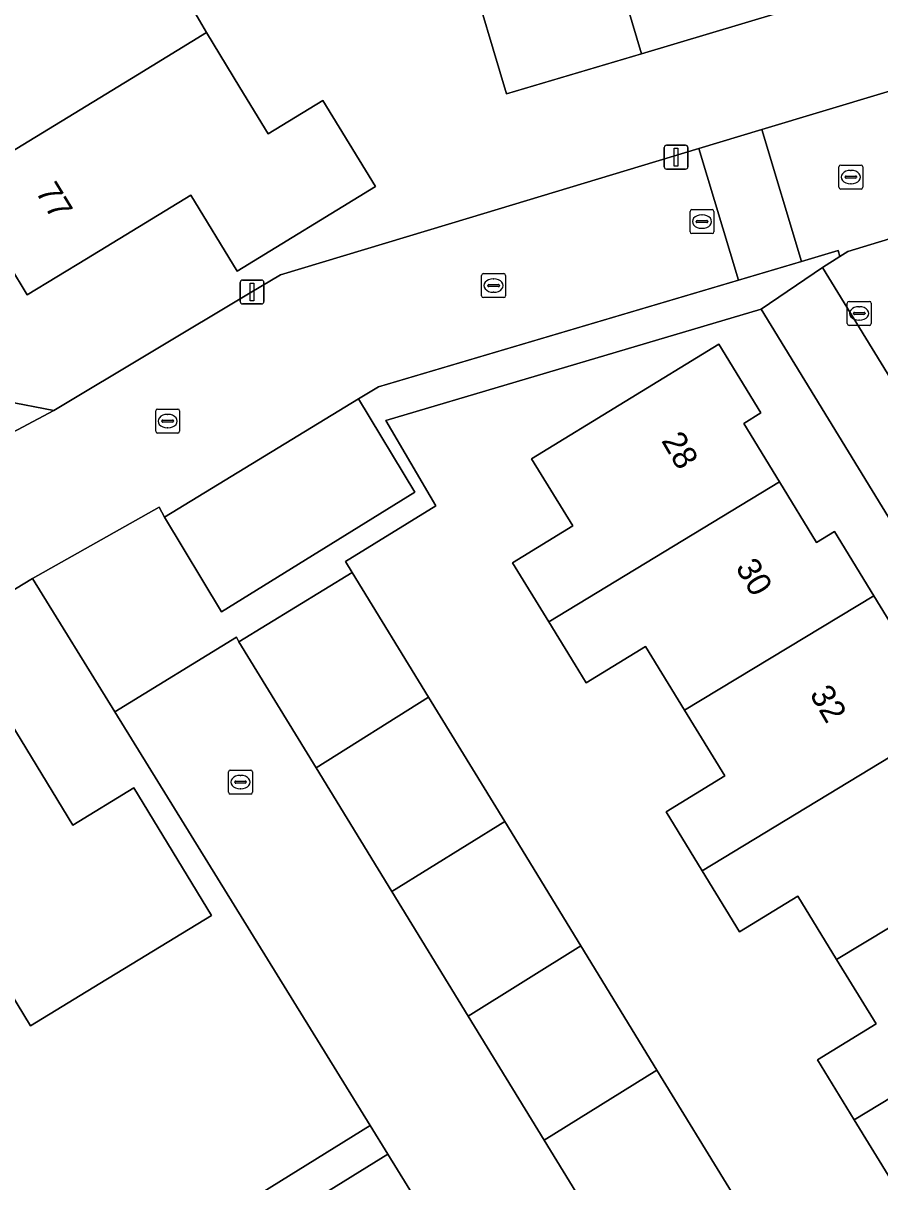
# Model space of a CAD drawing. Extents: x 157767 to 159172, y 387839 to 389425.
# Drawn here: x 158329.78 to 158365.56, y 388439.77 to 388488.15 of the extents above; entities that cross this region are included whole.
import ezdxf

# ---------------------------------------------------------------- set-up
doc = ezdxf.new("R2010")
doc.units = 0
for name, color, linetype in [('IMGEO_Erf', 7, 'Continuous'), ('IMGEO_Groenvoorziening', 7, 'Continuous'), ('IMGEO_Kolk', 7, 'Continuous'), ('IMGEO_Lichtmast', 7, 'Continuous'), ('IMGEO_Muur', 7, 'Continuous'), ('IMGEO_Pand', 7, 'Continuous'), ('IMGEO_Pand_nummerreeks', 7, 'Continuous'), ('IMGEO_Parkeervlak_open', 7, 'Continuous'), ('IMGEO_Rijbaan_lokaal_open', 7, 'Continuous'), ('IMGEO_Rioolput', 7, 'Continuous'), ('IMGEO_Voetpad_open', 7, 'Continuous')]:
    doc.layers.add(name, color=color, linetype=linetype)

msp = doc.modelspace()

# ---------------------------------------------------------------- linework, layer by layer
at = {"layer": 'IMGEO_Erf'}
for points in [[(158366.103, 388530.873), (158360.131, 388540.602), (158358.142, 388543.842), (158322.626, 388522.238), (158314.356, 388517.207), (158305.25, 388511.668), (158312.315, 388500), (158328.006, 388474.085), (158329.045, 388472.369), (158331.064, 388471.977), (158339.268, 388476.896), (158340.523, 388477.649), (158348.428, 388480.03), (158358.003, 388482.915), (158360.636, 388483.708), (158378.748, 388489.164), (158379.851, 388490.943), (158379.808, 388491.087), (158377.122, 388500)], [(158361.287, 388488.568), (158355.6, 388486.877), (158349.963, 388485.2), (158348.337, 388490.669)], [(158336.175, 388489.943), (158337.431, 388487.759), (158338.833, 388485.461), (158340.011, 388483.53), (158342.296, 388484.924), (158344.491, 388481.327), (158338.715, 388477.802), (158336.782, 388480.97), (158332.421, 388478.309), (158329.954, 388476.803), (158329.204, 388478.033), (158328.914, 388477.856), (158328.289, 388478.881), (158328.58, 388479.059), (158327.113, 388481.461), (158324.343, 388485.996), (158331.209, 388490.187)], [(158387.122, 388432.9), (158360.606, 388476.208), (158355.812, 388474.787), (158344.923, 388471.558), (158347.021, 388467.993), (158343.245, 388465.675), (158343.518, 388465.214), (158346.711, 388460.003), (158349.892, 388454.812), (158353.074, 388449.619), (158356.25, 388444.435), (158359.407, 388439.283), (158362.687, 388433.93), (158357.959, 388431.033), (158358.692, 388429.898), (158361.544, 388425.275), (158364.397, 388420.65), (158359.169, 388417.424), (158356.304, 388422.069), (158353.464, 388426.673), (158353.717, 388426.829), (158345.01, 388440.931), (158327.37, 388430.016)], [(158366.012, 388439.874), (158364.49, 388442.359), (158362.954, 388444.865), (158365.4, 388446.364), (158363.749, 388449.058), (158362.131, 388451.699), (158359.7, 388450.209), (158358.134, 388452.764), (158356.631, 388455.218), (158359.087, 388456.723), (158357.404, 388459.47), (158355.775, 388462.128), (158353.297, 388460.609), (158352.836, 388461.362), (158351.739, 388463.153), (158350.224, 388465.625), (158352.735, 388467.164), (158351.017, 388469.967), (158358.834, 388474.756), (158360.595, 388471.88), (158359.874, 388471.438), (158361.367, 388469.002), (158362.915, 388466.474), (158363.659, 388466.93), (158365.308, 388464.239), (158367.006, 388461.467)], [(158328.833, 388459.635), (158331.861, 388454.669), (158334.402, 388456.218), (158337.647, 388450.897), (158333.378, 388448.295), (158333.235, 388448.207), (158330.088, 388446.289), (158328.645, 388448.655)]]:
    msp.add_lwpolyline(points, dxfattribs=at)
msp.add_lwpolyline([(158334.852, 388436.275), (158344.271, 388442.128), (158333.608, 388459.397), (158330.168, 388464.968), (158255.92, 388419.848), (158255.073, 388417.271), (158254.463, 388415.416), (158258.254, 388409.185), (158259.825, 388406.604), (158265.321, 388397.571), (158266.938, 388394.918), (158298.48, 388413.756), (158296.533, 388416.95), (158304.157, 388421.599), (158306.105, 388418.404)], close=True, dxfattribs=at)
at = {"layer": 'IMGEO_Groenvoorziening'}
msp.add_lwpolyline([(158374.394, 388481.687), (158366.919, 388479.436), (158364.221, 388478.624), (158363.886, 388478.411), (158363.169, 388477.953), (158368.328, 388469.526)], dxfattribs=at)
at = {"layer": 'IMGEO_Kolk'}
for p, q in [((158363.849, 388481.3), (158363.849, 388482.152)), ((158363.924, 388482.226), (158364.776, 388482.226)), ((158364.85, 388482.152), (158364.85, 388481.3)), ((158364.108, 388481.72), (158364.108, 388481.732)), ((158364.546, 388481.683), (158364.148, 388481.683)), ((158364.151, 388481.769), (158364.549, 388481.769)), ((158364.337, 388482.006), (158364.362, 388482.006)), ((158364.592, 388481.732), (158364.592, 388481.72)), ((158364.776, 388481.226), (158363.924, 388481.226)), ((158364.36, 388481.446), (158364.335, 388481.446)), ((158348.927, 388476.77), (158348.927, 388477.622)), ((158349.002, 388477.696), (158349.854, 388477.696)), ((158349.229, 388477.239), (158349.627, 388477.239)), ((158349.415, 388477.476), (158349.44, 388477.476)), ((158349.928, 388477.622), (158349.928, 388476.77)), ((158349.186, 388477.19), (158349.186, 388477.202)), ((158349.624, 388477.153), (158349.226, 388477.153)), ((158349.438, 388476.916), (158349.413, 388476.916)), ((158349.67, 388477.202), (158349.67, 388477.19)), ((158349.854, 388476.696), (158349.002, 388476.696)), ((158335.315, 388471.111), (158335.315, 388471.963)), ((158335.39, 388472.037), (158336.242, 388472.037)), ((158336.316, 388471.963), (158336.316, 388471.111)), ((158335.574, 388471.531), (158335.574, 388471.543)), ((158336.012, 388471.494), (158335.614, 388471.494)), ((158335.617, 388471.58), (158336.015, 388471.58)), ((158335.803, 388471.817), (158335.828, 388471.817)), ((158336.058, 388471.543), (158336.058, 388471.531)), ((158336.242, 388471.037), (158335.39, 388471.037)), ((158335.826, 388471.257), (158335.801, 388471.257)), ((158338.432, 388456.963), (158339.284, 388456.963)), ((158338.357, 388456.037), (158338.357, 388456.889)), ((158338.616, 388456.457), (158338.616, 388456.469)), ((158339.054, 388456.42), (158338.656, 388456.42)), ((158338.659, 388456.506), (158339.057, 388456.506)), ((158338.845, 388456.743), (158338.87, 388456.743)), ((158339.1, 388456.469), (158339.1, 388456.457)), ((158339.358, 388456.889), (158339.358, 388456.037)), ((158339.284, 388455.963), (158338.432, 388455.963)), ((158338.868, 388456.183), (158338.843, 388456.183))]:
    msp.add_line(p, q, dxfattribs=at)
for points in [[(158363.849, 388481.3), (158363.849, 388482.152)], [(158363.924, 388482.226), (158364.776, 388482.226)], [(158364.85, 388482.152), (158364.85, 388481.3)], [(158364.776, 388481.226), (158363.924, 388481.226)], [(158348.927, 388476.77), (158348.927, 388477.622)], [(158349.002, 388477.696), (158349.854, 388477.696)], [(158349.928, 388477.622), (158349.928, 388476.77)], [(158349.854, 388476.696), (158349.002, 388476.696)], [(158335.315, 388471.111), (158335.315, 388471.963)], [(158335.39, 388472.037), (158336.242, 388472.037)], [(158336.316, 388471.963), (158336.316, 388471.111)], [(158336.242, 388471.037), (158335.39, 388471.037)], [(158338.432, 388456.963), (158339.284, 388456.963)], [(158338.357, 388456.037), (158338.357, 388456.889)], [(158339.358, 388456.889), (158339.358, 388456.037)], [(158339.284, 388455.963), (158338.432, 388455.963)]]:
    msp.add_lwpolyline(points, dxfattribs=at)
for centre, radius, start, end in [((158363.926, 388482.15), 0.0765, 91.552, 178.448), ((158363.926, 388482.15), 0.0765, 91.552, 178.448), ((158364.774, 388482.15), 0.0765, 1.552, 88.448), ((158364.774, 388482.15), 0.0765, 1.552, 88.448), ((158364.148, 388481.729), 0.0403, 85.8775, 175.7526), ((158364.145, 388481.719), 0.0366, 178.938, 274.7102), ((158364.549, 388481.726), 0.043, 264.8664, 352.4533), ((158364.553, 388481.731), 0.0386, 1.7309, 96.639), ((158363.926, 388481.302), 0.0765, 181.552, 268.448), ((158363.926, 388481.302), 0.0765, 181.552, 268.448), ((158364.774, 388481.302), 0.0765, 271.552, 358.448), ((158364.774, 388481.302), 0.0765, 271.552, 358.448), ((158349.004, 388477.62), 0.0765, 91.552, 178.448), ((158349.004, 388477.62), 0.0765, 91.552, 178.448), ((158349.226, 388477.199), 0.0403, 85.8775, 175.7526), ((158349.631, 388477.201), 0.0386, 1.7309, 96.639), ((158349.852, 388477.62), 0.0765, 1.552, 88.448), ((158349.852, 388477.62), 0.0765, 1.552, 88.448), ((158349.004, 388476.772), 0.0765, 181.552, 268.448), ((158349.004, 388476.772), 0.0765, 181.552, 268.448), ((158349.223, 388477.189), 0.0366, 178.938, 274.7102), ((158349.627, 388477.196), 0.043, 264.8664, 352.4533), ((158349.852, 388476.772), 0.0765, 271.552, 358.448), ((158349.852, 388476.772), 0.0765, 271.552, 358.448), ((158335.392, 388471.961), 0.0765, 91.552, 178.448), ((158335.392, 388471.961), 0.0765, 91.552, 178.448), ((158336.24, 388471.961), 0.0765, 1.552, 88.448), ((158336.24, 388471.961), 0.0765, 1.552, 88.448), ((158335.614, 388471.54), 0.0403, 85.8775, 175.7526), ((158335.611, 388471.53), 0.0366, 178.938, 274.7102), ((158336.015, 388471.537), 0.043, 264.8664, 352.4533), ((158336.019, 388471.542), 0.0386, 1.7309, 96.639), ((158335.392, 388471.113), 0.0765, 181.552, 268.448), ((158335.392, 388471.113), 0.0765, 181.552, 268.448), ((158336.24, 388471.113), 0.0765, 271.552, 358.448), ((158336.24, 388471.113), 0.0765, 271.552, 358.448), ((158338.434, 388456.887), 0.0765, 91.552, 178.448), ((158338.434, 388456.887), 0.0765, 91.552, 178.448), ((158339.282, 388456.887), 0.0765, 1.552, 88.448), ((158339.282, 388456.887), 0.0765, 1.552, 88.448), ((158338.656, 388456.466), 0.0403, 85.8775, 175.7526), ((158338.653, 388456.456), 0.0366, 178.938, 274.7102), ((158339.057, 388456.463), 0.043, 264.8664, 352.4533), ((158339.061, 388456.468), 0.0386, 1.7309, 96.639), ((158338.434, 388456.039), 0.0765, 181.552, 268.448), ((158338.434, 388456.039), 0.0765, 181.552, 268.448), ((158339.282, 388456.039), 0.0765, 271.552, 358.448), ((158339.282, 388456.039), 0.0765, 271.552, 358.448)]:
    msp.add_arc(centre, radius, start, end, dxfattribs=at)
for centre, major_axis, ratio, start_param, end_param in [((158364.336, 388481.726), (-0.387, 0.002), 0.722429, 4.712389, 7.853982), ((158364.361, 388481.726), (-0.39, 0.002), 0.717154, 1.570796, 4.712389), ((158349.414, 388477.196), (-0.387, 0.002), 0.722429, 4.712389, 7.853982), ((158349.439, 388477.196), (-0.39, 0.002), 0.717154, 1.570796, 4.712389), ((158335.802, 388471.537), (-0.387, 0.002), 0.722429, 4.712389, 7.853982), ((158335.827, 388471.537), (-0.39, 0.002), 0.717154, 1.570796, 4.712389), ((158338.844, 388456.463), (-0.387, 0.002), 0.722429, 4.712389, 7.853982), ((158338.869, 388456.463), (-0.39, 0.002), 0.717154, 1.570796, 4.712389)]:
    msp.add_ellipse(centre, major_axis=major_axis, ratio=ratio, start_param=start_param, end_param=end_param, dxfattribs=at)
at = {"layer": 'IMGEO_Lichtmast'}
for p, q in [((158356.652, 388483.057), (158357.442, 388483.057)), ((158357.442, 388483.057), (158356.652, 388483.057)), ((158356.552, 388482.157), (158356.552, 388482.957)), ((158356.552, 388482.957), (158356.552, 388482.157)), ((158357.542, 388482.957), (158357.542, 388482.157)), ((158357.542, 388482.157), (158357.542, 388482.957)), ((158357.442, 388482.057), (158356.652, 388482.057)), ((158356.652, 388482.057), (158357.442, 388482.057)), ((158338.847, 388476.528), (158338.847, 388477.328)), ((158338.847, 388477.328), (158338.847, 388476.528)), ((158338.947, 388477.428), (158339.737, 388477.428)), ((158339.737, 388477.428), (158338.947, 388477.428)), ((158339.837, 388477.328), (158339.837, 388476.528)), ((158339.837, 388476.528), (158339.837, 388477.328)), ((158339.737, 388476.428), (158338.947, 388476.428)), ((158338.947, 388476.428), (158339.737, 388476.428))]:
    msp.add_line(p, q, dxfattribs=at)
for points in [[(158356.972, 388482.932), (158357.122, 388482.932), (158357.122, 388482.182), (158356.972, 388482.182), (158356.972, 388482.932)], [(158339.267, 388477.303), (158339.417, 388477.303), (158339.417, 388476.553), (158339.267, 388476.553), (158339.267, 388477.303)]]:
    msp.add_lwpolyline(points, dxfattribs=at)
for centre, start, end in [((158356.652, 388482.957), 90, 180), ((158356.652, 388482.957), 90, 180), ((158357.442, 388482.957), 0, 90), ((158357.442, 388482.957), 360, 90), ((158356.652, 388482.157), 180, 270), ((158356.652, 388482.157), 180, 270), ((158357.442, 388482.157), 270, 0), ((158357.442, 388482.157), 270, 0), ((158338.947, 388477.328), 90, 180), ((158338.947, 388477.328), 90, 180), ((158339.737, 388477.328), 0, 90), ((158339.737, 388477.328), 360, 90), ((158338.947, 388476.528), 180, 270), ((158338.947, 388476.528), 180, 270), ((158339.737, 388476.528), 270, 0), ((158339.737, 388476.528), 270, 0)]:
    msp.add_arc(centre, 0.1, start, end, dxfattribs=at)
at = {"layer": 'IMGEO_Muur'}
for points in [[(158339.268, 388476.896), (158340.523, 388477.649), (158348.428, 388480.03)], [(158355.812, 388474.787), (158344.923, 388471.558), (158347.021, 388467.993), (158343.245, 388465.675)]]:
    msp.add_lwpolyline(points, dxfattribs=at)
at = {"layer": 'IMGEO_Pand'}
for points in [[(158355.6, 388486.877), (158361.287, 388488.568), (158359.655, 388494.056), (158362.309, 388494.845), (158360.774, 388500), (158360.504, 388500.908), (158358.61, 388500.345), (158357.695, 388500), (158358.469, 388497.399), (158352.957, 388495.76)], [(158352.957, 388495.76), (158352.323, 388497.89), (158346.806, 388496.248), (158346.658, 388496.746), (158343.719, 388495.873), (158344.091, 388494.623), (158345.515, 388489.83), (158348.337, 388490.669), (158349.963, 388485.2), (158355.6, 388486.877)], [(158336.175, 388489.943), (158334.984, 388491.895), (158337.325, 388493.324), (158335.148, 388496.89), (158329.3, 388493.314), (158331.209, 388490.187), (158324.343, 388485.996), (158327.113, 388481.461), (158334.551, 388485.99), (158337.431, 388487.759)], [(158327.113, 388481.461), (158328.58, 388479.059), (158328.289, 388478.881), (158328.914, 388477.856), (158329.204, 388478.033), (158329.954, 388476.803), (158332.421, 388478.309), (158336.782, 388480.97), (158338.715, 388477.802), (158344.491, 388481.327), (158342.296, 388484.924), (158340.011, 388483.53), (158338.833, 388485.461), (158337.431, 388487.759), (158334.551, 388485.99)], [(158351.739, 388463.153), (158361.367, 388469.002), (158359.874, 388471.438), (158360.595, 388471.88), (158358.834, 388474.756), (158351.017, 388469.967), (158352.735, 388467.164), (158350.224, 388465.625)], [(158351.739, 388463.153), (158352.836, 388461.362), (158353.297, 388460.609), (158355.775, 388462.128), (158357.404, 388459.47), (158365.308, 388464.239), (158363.659, 388466.93), (158362.915, 388466.474), (158361.367, 388469.002)], [(158342.011, 388457.06), (158346.711, 388460.003), (158343.518, 388465.214), (158338.79, 388462.317)], [(158357.404, 388459.47), (158359.087, 388456.723), (158356.631, 388455.218), (158358.134, 388452.764), (158367.758, 388458.585), (158366.269, 388461.015), (158367.006, 388461.467), (158365.308, 388464.239)], [(158342.011, 388457.06), (158345.179, 388451.89), (158349.892, 388454.812), (158346.711, 388460.003)], [(158334.402, 388456.218), (158331.861, 388454.669), (158328.833, 388459.635), (158323.815, 388456.575), (158328.645, 388448.655), (158330.088, 388446.289), (158333.235, 388448.207), (158333.378, 388448.295), (158337.647, 388450.897)], [(158363.749, 388449.058), (158371.693, 388453.838), (158370.053, 388456.515), (158369.307, 388456.057), (158367.758, 388458.585), (158358.134, 388452.764), (158359.7, 388450.209), (158362.131, 388451.699)], [(158345.179, 388451.89), (158348.364, 388446.693), (158353.074, 388449.619), (158349.892, 388454.812)], [(158363.749, 388449.058), (158365.4, 388446.364), (158362.954, 388444.865), (158364.49, 388442.359), (158374.148, 388448.202), (158372.662, 388450.626), (158373.389, 388451.071), (158371.693, 388453.838)], [(158356.25, 388444.435), (158353.074, 388449.619), (158348.364, 388446.693), (158351.539, 388441.51)], [(158377.138, 388442.93), (158378.01, 388443.465), (158376.38, 388446.126), (158375.682, 388445.699), (158374.148, 388448.202), (158364.49, 388442.359), (158366.012, 388439.874), (158368.47, 388441.381), (158370.15, 388438.64)], [(158359.407, 388439.283), (158356.25, 388444.435), (158351.539, 388441.51), (158354.715, 388436.327)]]:
    msp.add_lwpolyline(points, close=True, dxfattribs=at)
at = {"layer": 'IMGEO_Parkeervlak_open'}
msp.add_lwpolyline([(158343.79, 388472.46), (158335.69, 388467.523), (158338.07, 388463.578), (158346.142, 388468.567)], close=True, dxfattribs=at)
at = {"layer": 'IMGEO_Rijbaan_lokaal_open'}
for points in [[(158309.761, 388490.79), (158322.072, 388470.559), (158323.674, 388468.061), (158331.064, 388471.977), (158329.045, 388472.369), (158328.006, 388474.085), (158312.315, 388500)], [(158255.92, 388419.848), (158330.168, 388464.968), (158335.456, 388467.942), (158335.69, 388467.523), (158343.79, 388472.46), (158344.619, 388472.966), (158359.657, 388477.426), (158358.003, 388482.915), (158348.428, 388480.03), (158340.523, 388477.649), (158339.268, 388476.896), (158331.064, 388471.977), (158323.674, 388468.061)]]:
    msp.add_lwpolyline(points, dxfattribs=at)
for points in [[(158379.446, 388483.21), (158380.606, 388483.556), (158382.634, 388482.447), (158380.065, 388491.06), (158379.808, 388491.087), (158379.851, 388490.943), (158378.748, 388489.164), (158360.636, 388483.708), (158362.294, 388478.208), (158363.813, 388478.659), (158363.886, 388478.411), (158364.221, 388478.624), (158366.919, 388479.436), (158374.394, 388481.687), (158374.972, 388481.861)], [(158359.657, 388477.426), (158362.294, 388478.208), (158360.636, 388483.708), (158358.003, 388482.915)], [(158348.364, 388446.693), (158345.179, 388451.89), (158342.011, 388457.06), (158338.79, 388462.317), (158338.695, 388462.519), (158333.608, 388459.397), (158344.271, 388442.128), (158345.01, 388440.931), (158353.717, 388426.829), (158358.692, 388429.898), (158357.959, 388431.033), (158354.715, 388436.327), (158351.539, 388441.51)]]:
    msp.add_lwpolyline(points, close=True, dxfattribs=at)
at = {"layer": 'IMGEO_Rioolput'}
for p, q in [((158357.631, 388479.44), (158357.631, 388480.292)), ((158357.706, 388480.366), (158358.558, 388480.366)), ((158358.119, 388480.146), (158358.144, 388480.146)), ((158358.632, 388480.292), (158358.632, 388479.44)), ((158357.89, 388479.86), (158357.89, 388479.872)), ((158358.328, 388479.823), (158357.93, 388479.823)), ((158357.933, 388479.909), (158358.331, 388479.909)), ((158358.374, 388479.872), (158358.374, 388479.86)), ((158358.558, 388479.366), (158357.706, 388479.366)), ((158358.142, 388479.586), (158358.117, 388479.586)), ((158364.199, 388475.608), (158364.199, 388476.46)), ((158364.274, 388476.534), (158365.126, 388476.534)), ((158364.687, 388476.314), (158364.712, 388476.314)), ((158365.2, 388476.46), (158365.2, 388475.608)), ((158364.458, 388476.028), (158364.458, 388476.04)), ((158364.896, 388475.991), (158364.498, 388475.991)), ((158364.501, 388476.077), (158364.899, 388476.077)), ((158364.942, 388476.04), (158364.942, 388476.028)), ((158365.126, 388475.534), (158364.274, 388475.534)), ((158364.71, 388475.754), (158364.685, 388475.754))]:
    msp.add_line(p, q, dxfattribs=at)
for points in [[(158357.631, 388479.44), (158357.631, 388480.292)], [(158357.706, 388480.366), (158358.558, 388480.366)], [(158358.632, 388480.292), (158358.632, 388479.44)], [(158358.558, 388479.366), (158357.706, 388479.366)], [(158364.199, 388475.608), (158364.199, 388476.46)], [(158364.274, 388476.534), (158365.126, 388476.534)], [(158365.2, 388476.46), (158365.2, 388475.608)], [(158365.126, 388475.534), (158364.274, 388475.534)]]:
    msp.add_lwpolyline(points, dxfattribs=at)
for centre, radius, start, end in [((158357.708, 388480.29), 0.0765, 91.552, 178.448), ((158357.708, 388480.29), 0.0765, 91.552, 178.448), ((158358.556, 388480.29), 0.0765, 1.552, 88.448), ((158358.556, 388480.29), 0.0765, 1.552, 88.448), ((158357.93, 388479.869), 0.0403, 85.8775, 175.7526), ((158357.927, 388479.859), 0.0366, 178.938, 274.7102), ((158358.331, 388479.866), 0.043, 264.8664, 352.4533), ((158358.335, 388479.871), 0.0386, 1.7309, 96.639), ((158357.708, 388479.442), 0.0765, 181.552, 268.448), ((158357.708, 388479.442), 0.0765, 181.552, 268.448), ((158358.556, 388479.442), 0.0765, 271.552, 358.448), ((158358.556, 388479.442), 0.0765, 271.552, 358.448), ((158364.276, 388476.458), 0.0765, 91.552, 178.448), ((158364.276, 388476.458), 0.0765, 91.552, 178.448), ((158365.124, 388476.458), 0.0765, 1.552, 88.448), ((158365.124, 388476.458), 0.0765, 1.552, 88.448), ((158364.498, 388476.037), 0.0403, 85.8775, 175.7526), ((158364.495, 388476.027), 0.0366, 178.938, 274.7102), ((158364.899, 388476.034), 0.043, 264.8664, 352.4533), ((158364.903, 388476.039), 0.0386, 1.7309, 96.639), ((158364.276, 388475.61), 0.0765, 181.552, 268.448), ((158364.276, 388475.61), 0.0765, 181.552, 268.448), ((158365.124, 388475.61), 0.0765, 271.552, 358.448), ((158365.124, 388475.61), 0.0765, 271.552, 358.448)]:
    msp.add_arc(centre, radius, start, end, dxfattribs=at)
for centre, major_axis, ratio, start_param, end_param in [((158358.118, 388479.866), (-0.387, 0.002), 0.722429, 4.712389, 7.853982), ((158358.143, 388479.866), (-0.39, 0.002), 0.717154, 1.570796, 4.712389), ((158364.686, 388476.034), (-0.387, 0.002), 0.722429, 4.712389, 7.853982), ((158364.711, 388476.034), (-0.39, 0.002), 0.717154, 1.570796, 4.712389)]:
    msp.add_ellipse(centre, major_axis=major_axis, ratio=ratio, start_param=start_param, end_param=end_param, dxfattribs=at)
at = {"layer": 'IMGEO_Voetpad_open'}
for points in [[(158343.518, 388465.214), (158343.245, 388465.675), (158347.021, 388467.993), (158344.923, 388471.558), (158355.812, 388474.787), (158360.606, 388476.208), (158363.169, 388477.953), (158363.886, 388478.411), (158363.813, 388478.659), (158362.294, 388478.208), (158359.657, 388477.426), (158344.619, 388472.966), (158343.79, 388472.46), (158346.142, 388468.567), (158338.07, 388463.578), (158335.69, 388467.523), (158335.456, 388467.942), (158330.168, 388464.968), (158333.608, 388459.397), (158338.695, 388462.519), (158338.79, 388462.317)], [(158368.328, 388469.526), (158363.169, 388477.953), (158360.606, 388476.208), (158387.122, 388432.9), (158389.777, 388434.491), (158389.076, 388435.636), (158380.059, 388450.365), (158377.747, 388454.141), (158371.364, 388464.566)]]:
    msp.add_lwpolyline(points, close=True, dxfattribs=at)
msp.add_lwpolyline([(158327.989, 388401.637), (158323.444, 388409.006), (158322.189, 388408.993), (158314.265, 388421.955), (158314.851, 388422.31), (158315.22, 388422.537), (158317.897, 388424.166), (158322.192, 388426.792), (158324.711, 388428.324), (158327.396, 388429.958), (158327.37, 388430.016), (158345.01, 388440.931), (158344.271, 388442.128), (158334.852, 388436.275), (158306.105, 388418.404), (158298.48, 388413.756), (158266.938, 388394.918)], dxfattribs=at)

# ---------------------------------------------------------------- texts
at = {"layer": 'IMGEO_Pand_nummerreeks'}
for s, rotation, p in [('77', 301.398, (158330.272, 388481.119)), ('28', 300.3296, (158356.414, 388470.721)), ('30', 300.3296, (158359.511, 388465.427)), ('32', 300.3296, (158362.606, 388460.138))]:
    msp.add_text(s, height=1, rotation=rotation, dxfattribs=at).set_placement(p)

doc.saveas('drawing.dxf')
